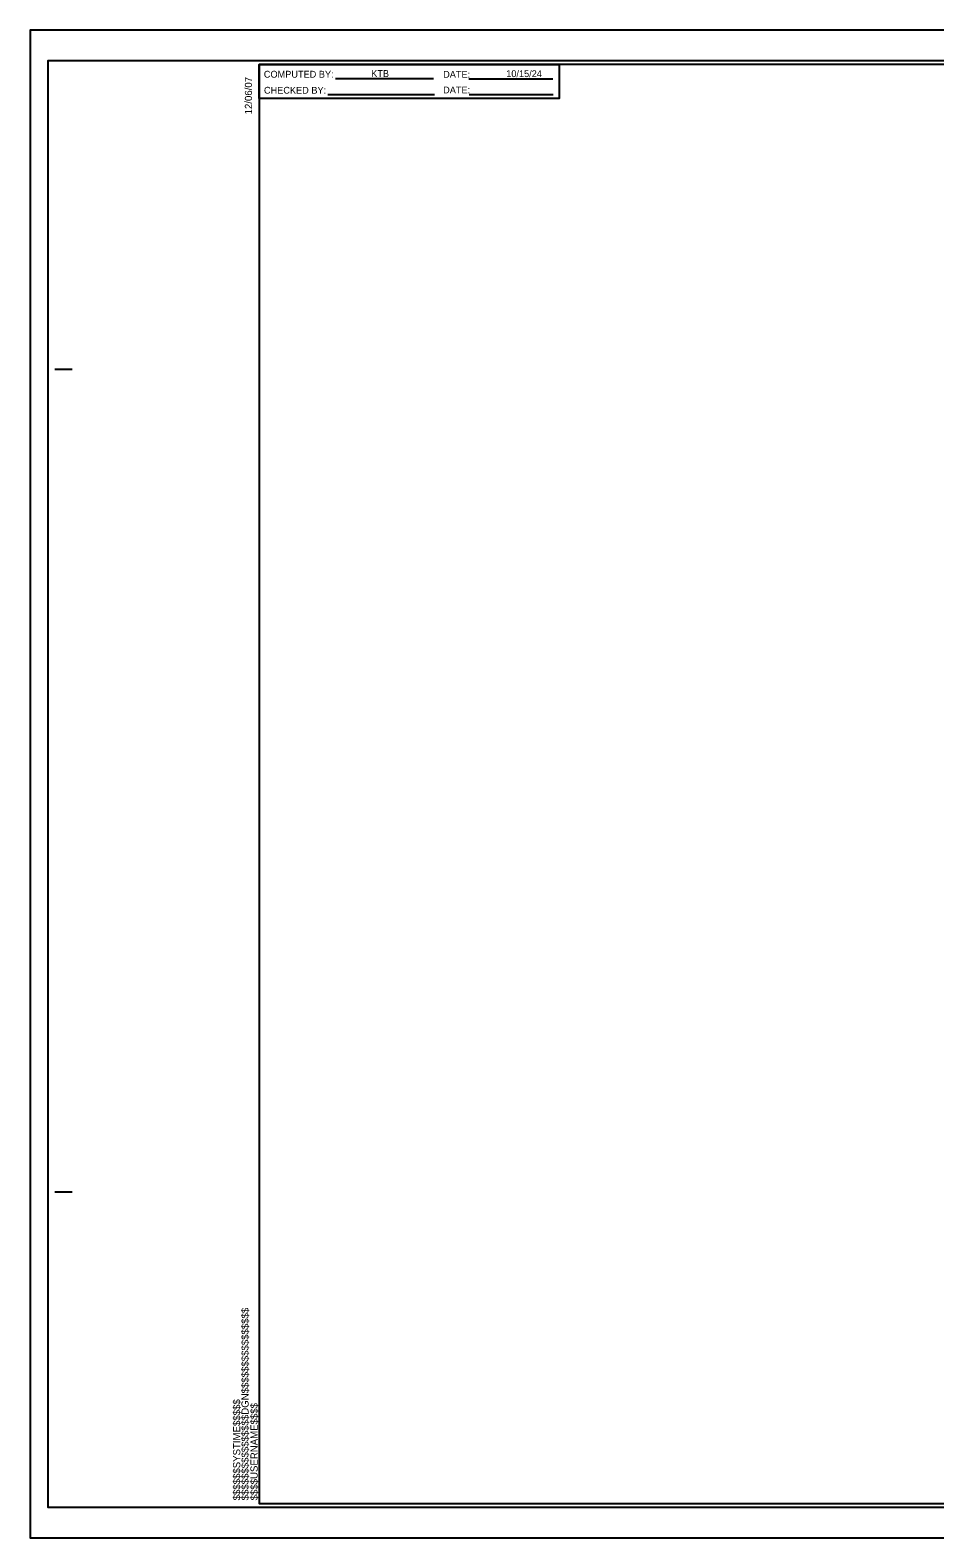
# Model space of a CAD drawing. Extents: x 575597 to 577281, y -53325 to -52225.
# Drawn here: x 575597 to 576257, y -53325 to -52225 of the extents above; entities that cross this region are included whole.
import ezdxf

# ---------------------------------------------------------------- set-up
doc = ezdxf.new("R2010")
doc.units = 0
for name, color, linetype in [('Sheet Cutting Line CELL', 7, 'Continuous'), ('Sheet Data Field CELL', 7, 'Continuous'), ('Sheet Plot Border Inside CELL', 7, 'Continuous'), ('Sheet Plot Border Outside CELL', 7, 'Continuous'), ('Sheet Summary Combination CELL', 7, 'Continuous')]:
    doc.layers.add(name, color=color, linetype=linetype)

msp = doc.modelspace()

# ---------------------------------------------------------------- linework, layer by layer
at = {"layer": 'Sheet Cutting Line CELL'}
for p, q in [((577280.6, -52224.8), (575596.6, -52224.8)), ((575596.6, -52224.8), (575596.6, -53324.8)), ((575596.6, -53324.8), (577280.6, -53324.8))]:
    msp.add_line(p, q, dxfattribs=at)
at = {"layer": 'Sheet Plot Border Inside CELL'}
msp.add_lwpolyline([(577276.1, -52247.3), (575609.6, -52247.3), (575609.6, -53302.4), (577276.1, -53302.4)], close=True, dxfattribs=at)
at = {"layer": 'Sheet Plot Border Outside CELL'}
msp.add_lwpolyline([(577280.6, -52224.8), (575596.6, -52224.8), (575596.6, -53324.8), (577280.6, -53324.8)], close=True, dxfattribs=at)
at = {"layer": 'Sheet Summary Combination CELL'}
for p, q in [((575819.3, -52260.2), (575890.8, -52260.2)), ((575916.6, -52260.4), (575978, -52260.4)), ((575813.8, -52271.9), (575891.5, -52271.9)), ((575916.8, -52271.9), (575978.2, -52271.9)), ((575614.7, -52472.3), (575627.2, -52472.3)), ((575614.7, -53072.3), (575627.2, -53072.3))]:
    msp.add_line(p, q, dxfattribs=at)
for points in [[(577263.6, -52249.8), (575763.6, -52249.8), (575763.6, -53299.8), (577263.6, -53299.8)], [(575763.6, -52249.8), (575982.6, -52249.8), (575982.6, -52274.8), (575763.6, -52274.8)]]:
    msp.add_lwpolyline(points, close=True, dxfattribs=at)

# ---------------------------------------------------------------- texts
at = {"layer": 'Sheet Data Field CELL'}
for s, p in [('KTB', (575845.4, -52259)), ('10/15/24', (575943.9, -52259.1))]:
    msp.add_text(s, height=5, dxfattribs=at).set_placement(p)
at = {"layer": 'Sheet Summary Combination CELL'}
for s, p in [('12/06/07', (575758.5, -52286.3)), ('$$$$$$$$$$$$$$$$DGN$$$$$$$$$$$$$$$$', (575756, -53297.5)), ('$$$$$$SYSTIME$$$$$', (575749.9, -53297.5)), ('$$$$USERNAME$$$$', (575762.6, -53297.5))]:
    msp.add_text(s, height=5.25, rotation=90, dxfattribs=at).set_placement(p)
for s, p in [('COMPUTED BY:', (575767.1, -52259.5)), ('DATE:', (575897.9, -52259.6)), ('CHECKED BY:', (575767.2, -52271.2)), ('DATE:', (575897.9, -52271))]:
    msp.add_text(s, height=5, dxfattribs=at).set_placement(p)

doc.saveas('drawing.dxf')
